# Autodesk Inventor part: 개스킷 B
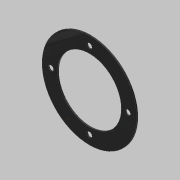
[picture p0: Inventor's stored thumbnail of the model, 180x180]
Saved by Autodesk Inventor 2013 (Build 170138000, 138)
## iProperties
Created: 2019-10
Part Number: 개스킷 B
Material: 고무
Document SubType Name: Modeling
Designer: mduedu
Density: 0.93 g/cm^3
Mass: 2.48562 g
Surface Area: 58.2294 cm^2
Volume: 2.67271 cm^3
Author: mduedu
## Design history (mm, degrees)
sketch "스케치1"
  geometry: C1 r 40 at (0, 0); C2 r 27 at (0, 0); 1 further point
  constraints: 2 centre point, 2 coincident
  dimensions: "d0" = 80 diameter of C1; "d1" = 54 diameter of C2
extrude "돌출1" new body sketch "스케치1" distance "d2" = 1; taper "d3" = 0 deg
sketch "스케치2" dims "d4" = 65
  geometry: C1 r 2.25 at (0, 32.5); 2 further points
  constraints: 2 vertical alignment, 1 centre point, 1 coincident, 2 other
  dimensions: "d5" = 4.5 diameter of C1
extrude "돌출2" cut sketch "스케치2" stored distance "d6" = 1; taper "d7" = 0 deg
node "솔리드1"
pattern_circular "원형 패턴1" dims angle "d9" = 360 deg
